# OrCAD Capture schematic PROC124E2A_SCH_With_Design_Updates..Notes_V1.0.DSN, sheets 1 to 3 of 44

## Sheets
1 23. CPSW RGMII_2 ETHERNET PHY: size C; title: CPSW RGMII_1 ETHERNET PHY; rev: E2A
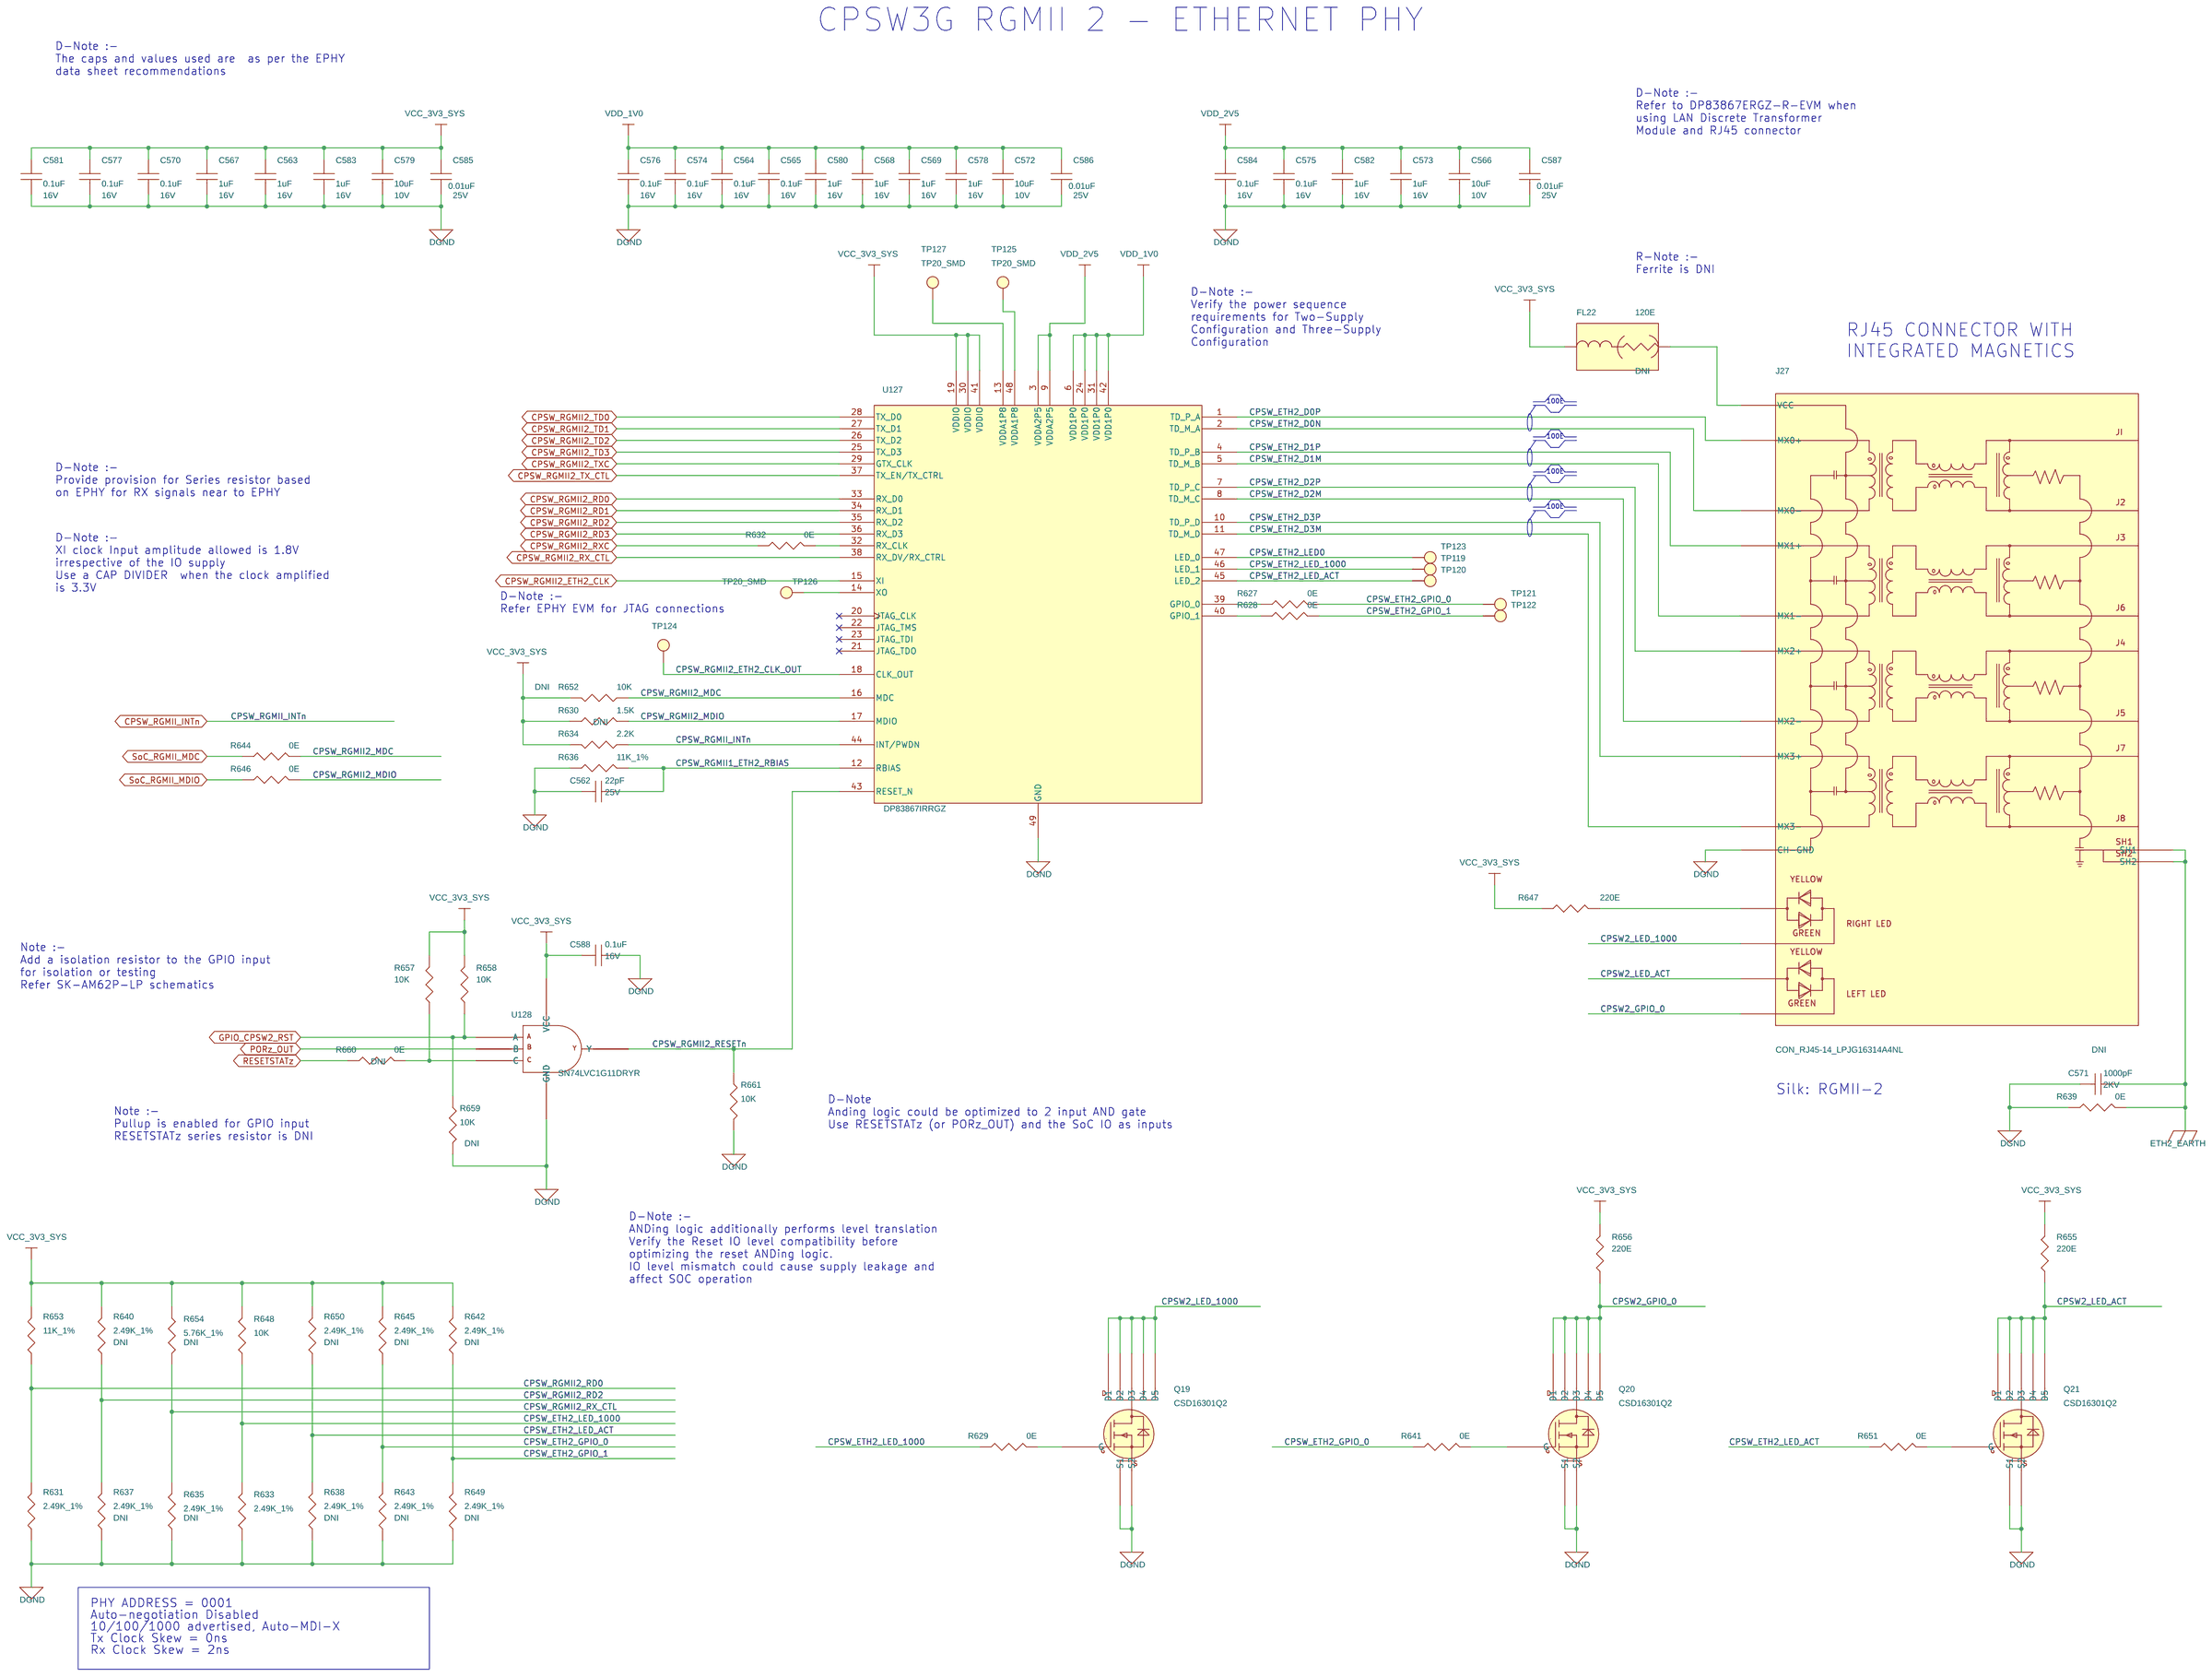
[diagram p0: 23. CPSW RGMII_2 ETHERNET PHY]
2 43. CAN FD WKUP SW: size C; title: CAN FD WKUP SW
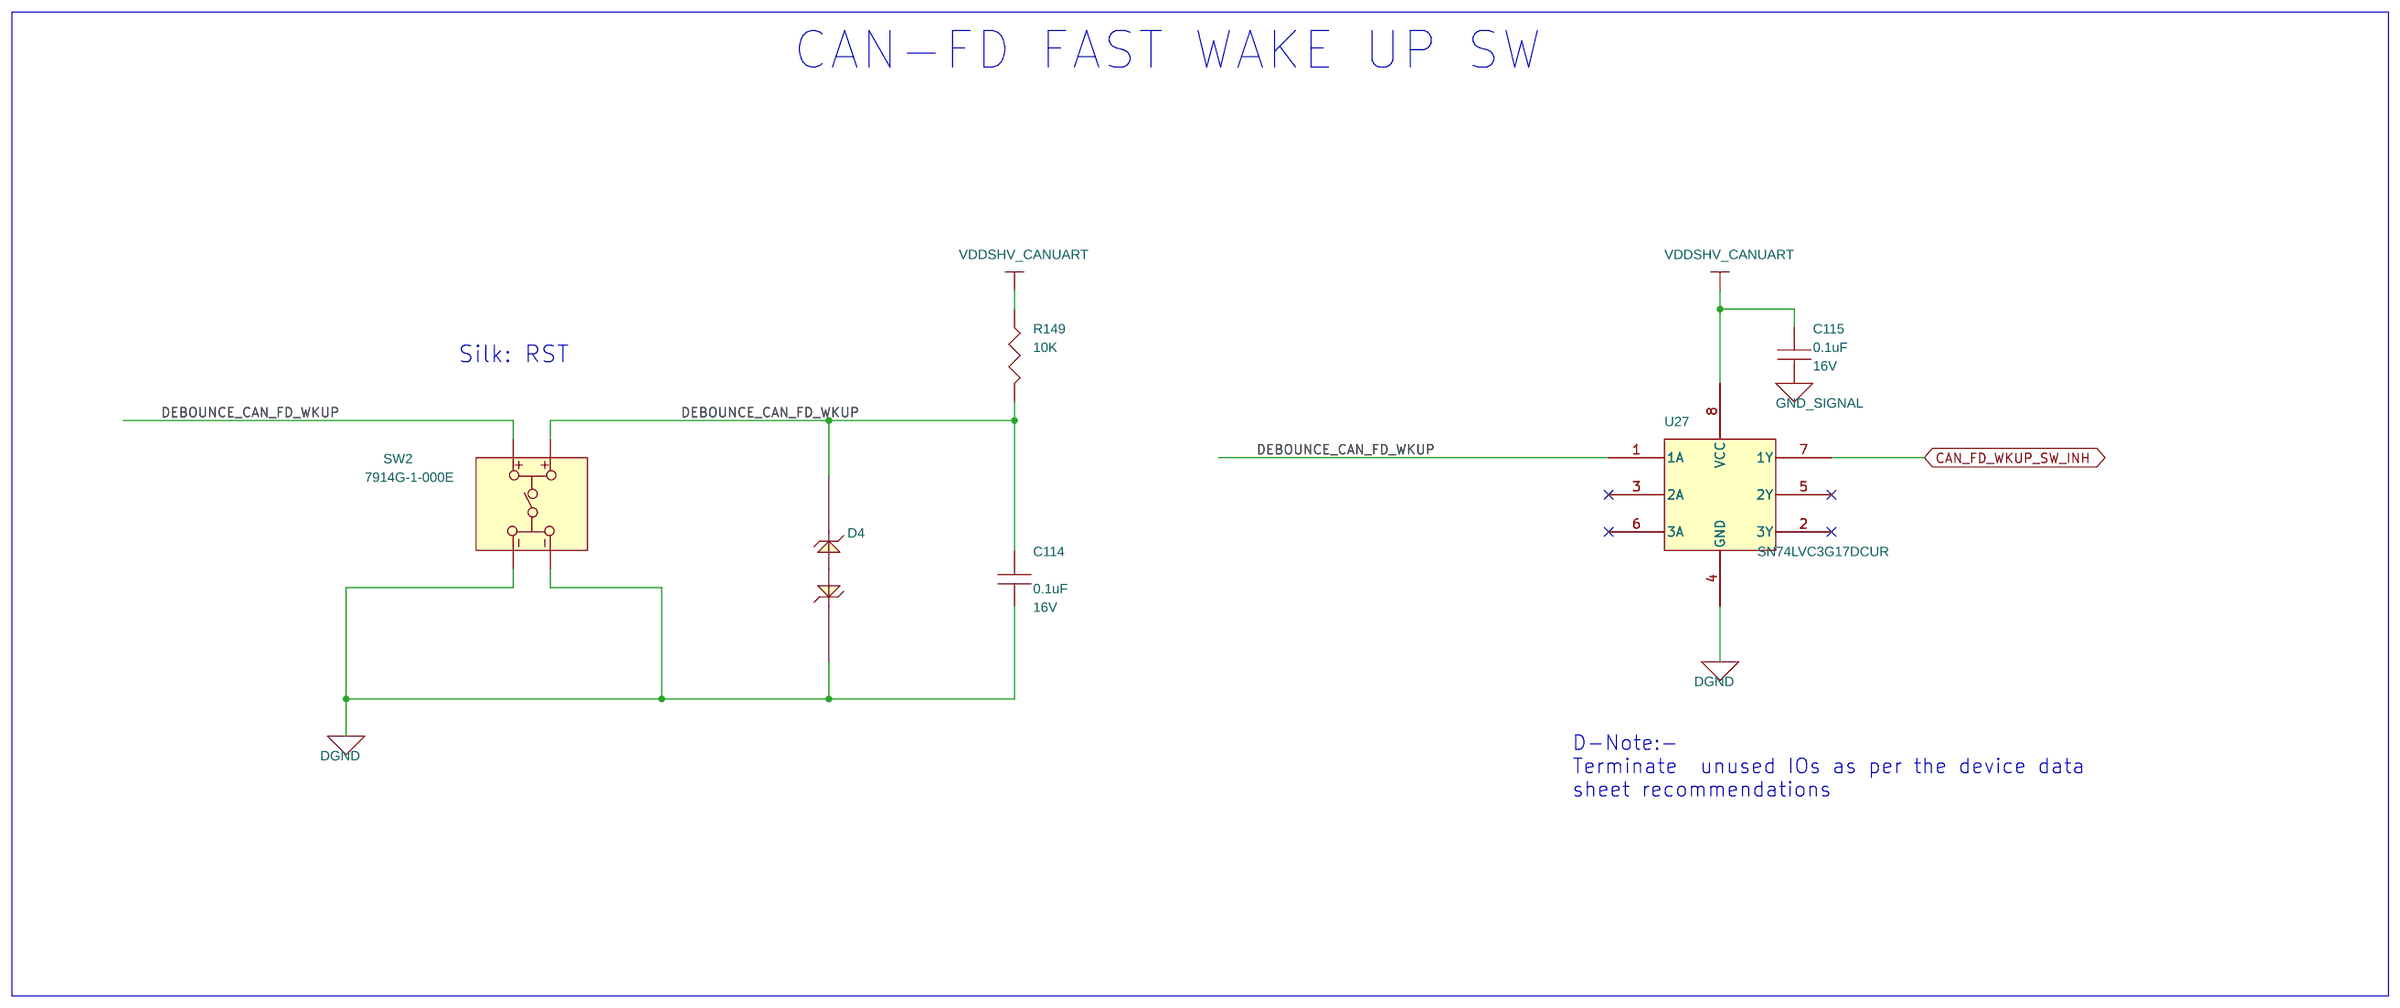
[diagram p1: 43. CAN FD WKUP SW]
3 16. LPDDR4 INTERFACE: size C; title: SOC LPDDR4 INTERFACE
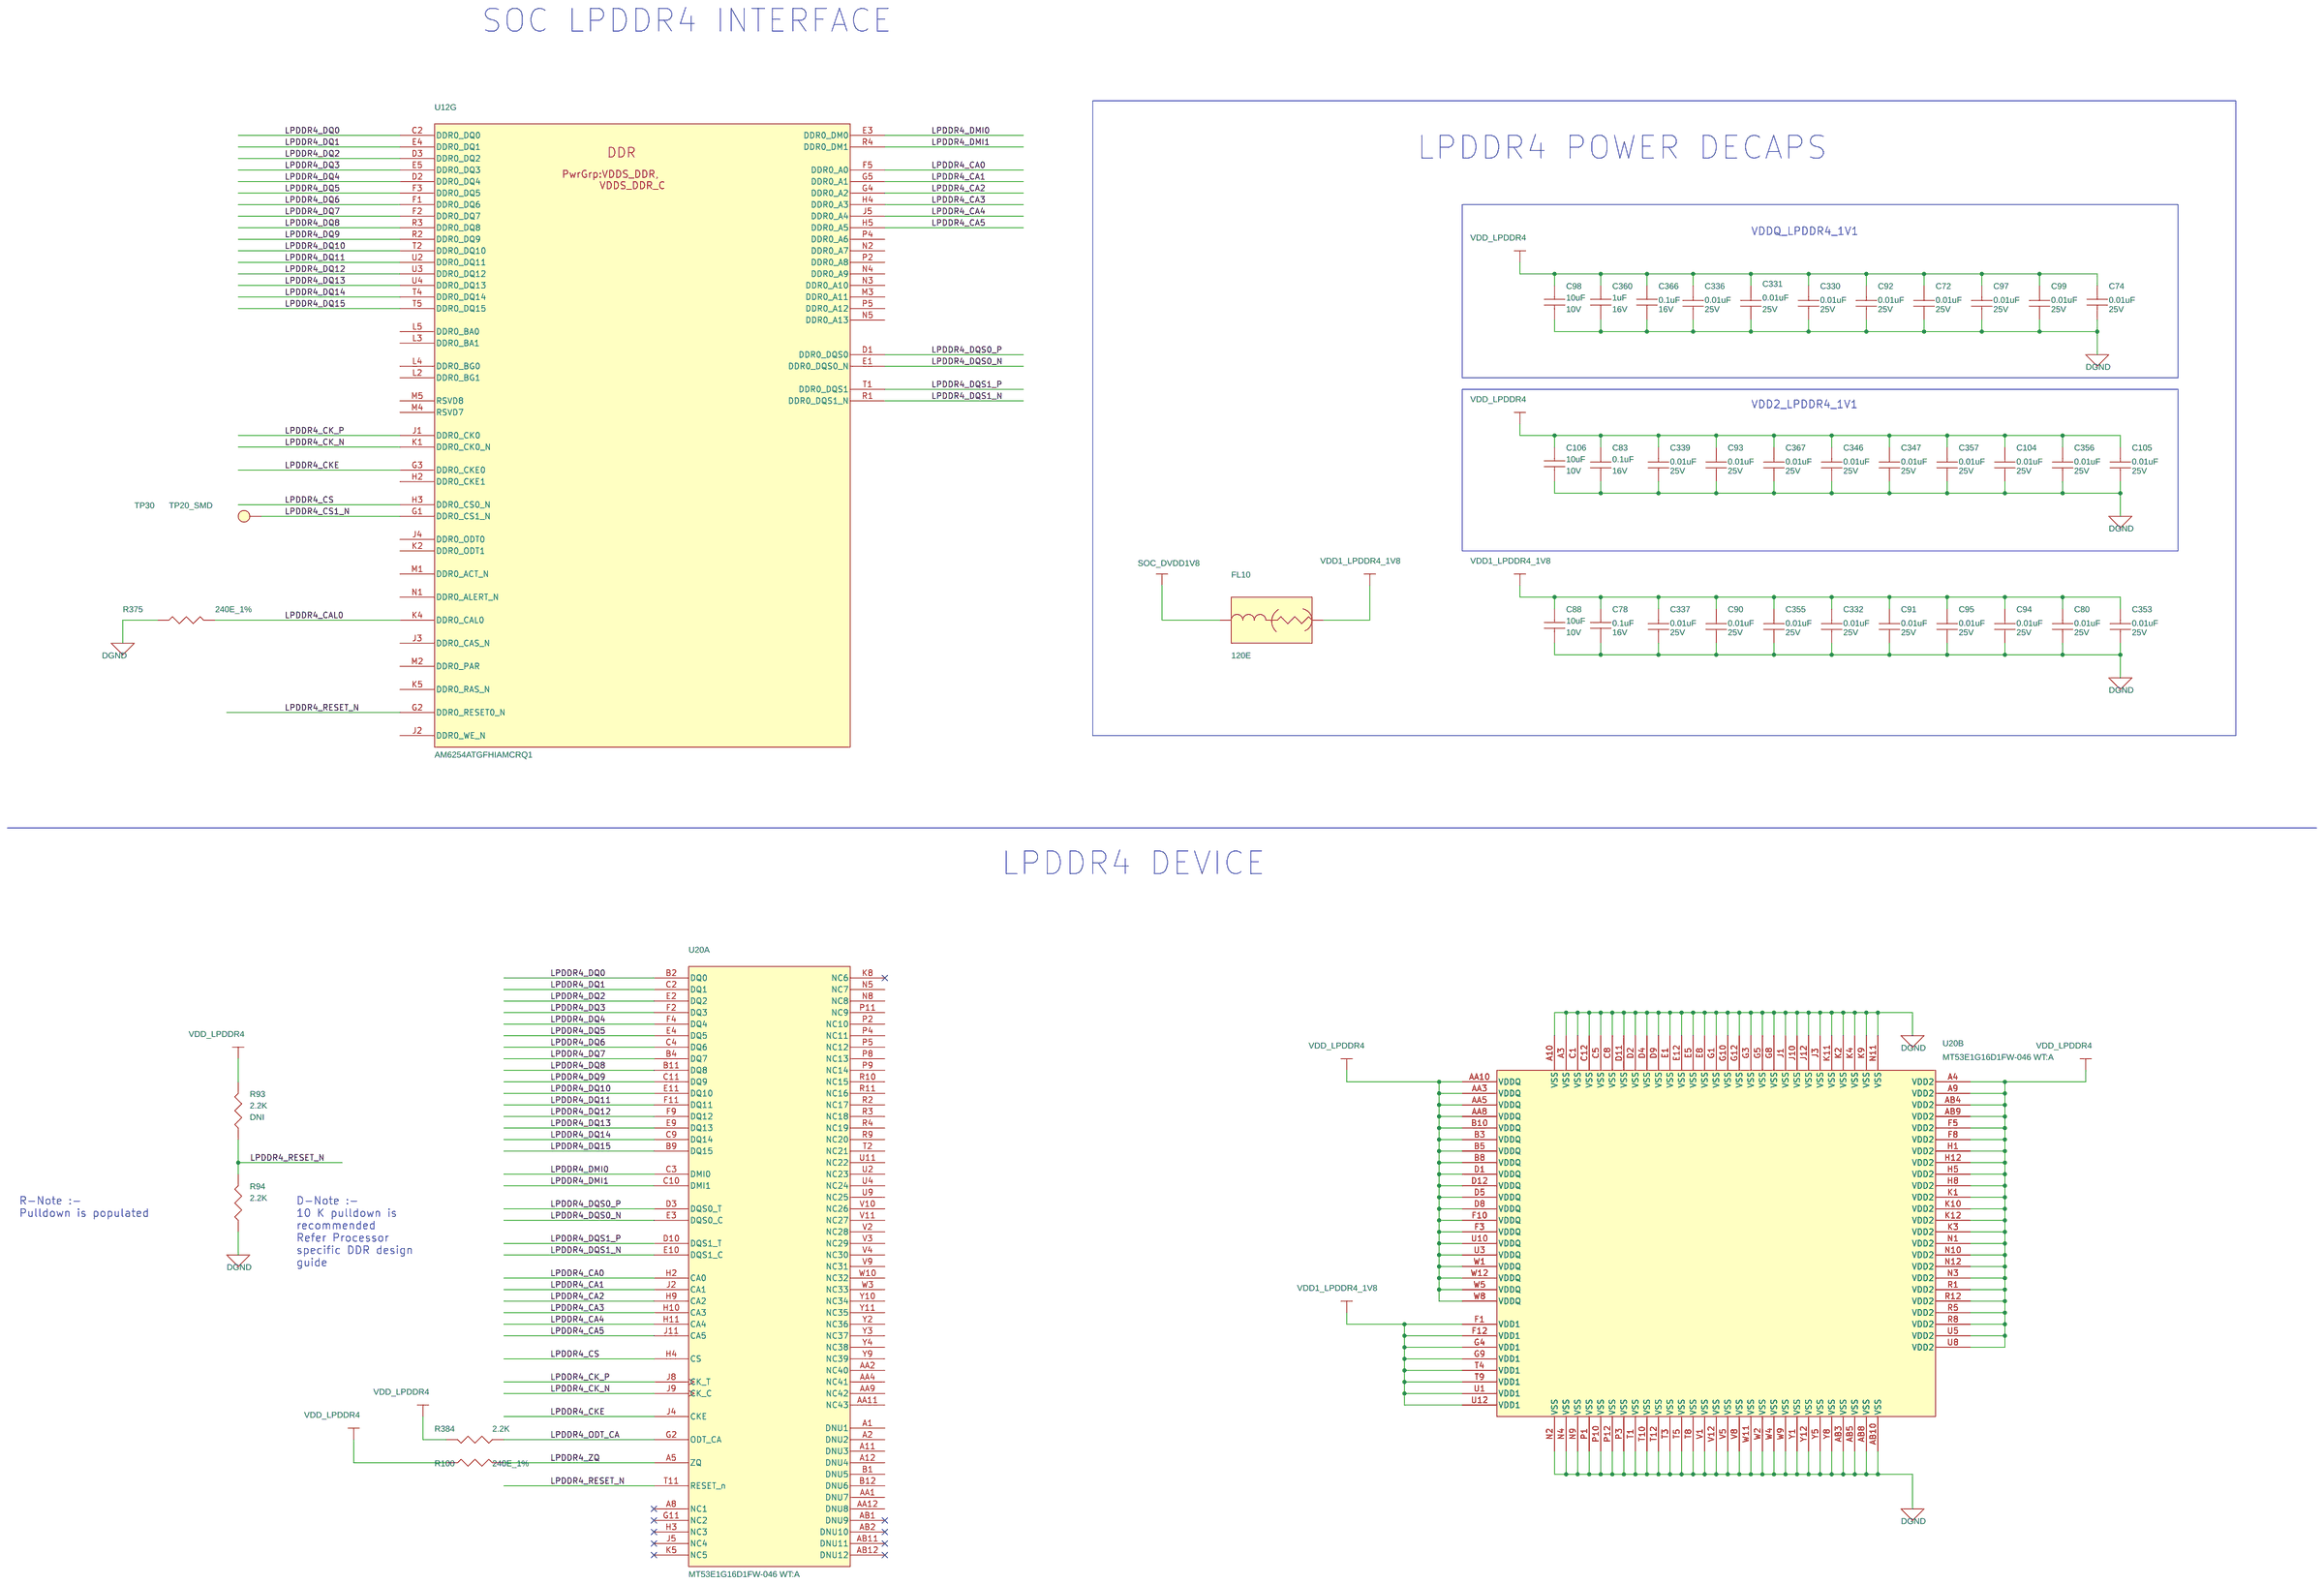
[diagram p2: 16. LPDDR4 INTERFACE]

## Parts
sheet 15. SOC POWER CAPS
U12  AM6254ATGFHIAMCRQ1  [FCBGA441_31-49_680X680_2-6]  (sections A,B,C,D,E,F,G,H,I,J,K,L,M,N,O,P,Q,R)
sheet 16. LPDDR4 INTERFACE
C72  0.01uF  [CAP0201_0-5]
C74  0.01uF  [CAP0201_0-5]
C78  0.1uF  [CAP0201_0-5]
C80  0.01uF  [CAP0201_0-5]
C83  0.1uF  [CAP0201_0-5]
C88  10uF  [CAP0402_0-75]
C90  0.01uF  [CAP0201_0-5]
C91  0.01uF  [CAP0201_0-5]
C92  0.01uF  [CAP0201_0-5]
C93  0.01uF  [CAP0201_0-5]
C94  0.01uF  [CAP0201_0-5]
C95  0.01uF  [CAP0201_0-5]
C97  0.01uF  [CAP0201_0-5]
C98  10uF  [CAP0402_0-75]
C99  0.01uF  [CAP0201_0-5]
C104  0.01uF  [CAP0201_0-5]
C105  0.01uF  [CAP0201_0-5]
C106  10uF  [CAP0402_0-75]
C330  0.01uF  [CAP0201_0-5]
C331  0.01uF  [CAP0201_0-5]
C332  0.01uF  [CAP0201_0-5]
C336  0.01uF  [CAP0201_0-5]
C337  0.01uF  [CAP0201_0-5]
C339  0.01uF  [CAP0201_0-5]
C346  0.01uF  [CAP0201_0-5]
C347  0.01uF  [CAP0201_0-5]
C353  0.01uF  [CAP0201_0-5]
C355  0.01uF  [CAP0201_0-5]
C356  0.01uF  [CAP0201_0-5]
C357  0.01uF  [CAP0201_0-5]
C360  1uF  [CAP0201_0-5]
C366  0.1uF  [CAP0201_0-5]
C367  0.01uF  [CAP0201_0-5]
FL10  120E  [EMIFIL_BLM15A_0402_0-6]
R93  2.2K  [RES0402_0-5]
R94  2.2K  [RES0402_0-5]
R100  240E_1%  [RES0402_0-5]
R375  240E_1%  [RES0402_0-5]
R384  2.2K  [RES0402_0-5]
TP30  TP20_SMD  [TP20_SMD]
U20  MT53E1G16D1FW-046 WT:A  [TFBGA200_MT53E1G16D1FW_400X570_1-1]  (sections A,B)
sheet 23. CPSW RGMII_2 ETHERNET PHY
C562  22pF  [CAP0201_0-5]
C563  1uF  [CAP0201_0-5]
C564  0.1uF  [CAP0201_0-5]
C565  0.1uF  [CAP0201_0-5]
C566  10uF  [CAP0402_0-75]
C567  1uF  [CAP0201_0-5]
C568  1uF  [CAP0201_0-5]
C569  1uF  [CAP0201_0-5]
C570  0.1uF  [CAP0201_0-5]
C571  1000pF  [CAP1206_1-75]
C572  10uF  [CAP0402_0-75]
C573  1uF  [CAP0201_0-5]
C574  0.1uF  [CAP0201_0-5]
C575  0.1uF  [CAP0201_0-5]
C576  0.1uF  [CAP0201_0-5]
C577  0.1uF  [CAP0201_0-5]
C578  1uF  [CAP0201_0-5]
C579  10uF  [CAP0402_0-75]
C580  1uF  [CAP0201_0-5]
C581  0.1uF  [CAP0201_0-5]
C582  1uF  [CAP0201_0-5]
C583  1uF  [CAP0201_0-5]
C584  0.1uF  [CAP0201_0-5]
C585  0.01uF  [CAP0201_0-5]
C586  0.01uF  [CAP0201_0-5]
C587  0.01uF  [CAP0201_0-5]
C588  0.1uF  [CAP0201_0-5]
FL22  120E  [EMIFIL_BLM15A_0402_0-6]
J27  CON_RJ45-14_LPJG16314A4NL  [CON_RJ45-14_LPJG16314A4NL_S_R_T_13-6]
Q19  CSD16301Q2  [WSON6_CSD13202Q2_80X80_0-8]
Q20  CSD16301Q2  [WSON6_CSD13202Q2_80X80_0-8]
Q21  CSD16301Q2  [WSON6_CSD13202Q2_80X80_0-8]
R627  0E  [RES0201_0-5]
R628  0E  [RES0201_0-5]
R629  0E  [RES0201_0-5]
R630  1.5K  [RES0201_0-5]
R631  2.49K_1%  [RES0402_0-5]
R632  0E  [RES0402_0-5]
R633  2.49K_1%  [RES0402_0-5]
R634  2.2K  [RES0201_0-5]
R635  2.49K_1%  [RES0402_0-5]
R636  11K_1%  [RES0402_0-5]
R637  2.49K_1%  [RES0402_0-5]
R638  2.49K_1%  [RES0402_0-5]
R639  0E  [RES0603_0-75]
R640  2.49K_1%  [RES0402_0-5]
R641  0E  [RES0201_0-5]
R642  2.49K_1%  [RES0402_0-5]
R643  2.49K_1%  [RES0402_0-5]
R644  0E  [RES0402_0-5]
R645  2.49K_1%  [RES0402_0-5]
R646  0E  [RES0402_0-5]
R647  220E  [RES0402_0-5]
R648  10K  [RES0201_0-5]
R649  2.49K_1%  [RES0402_0-5]
R650  2.49K_1%  [RES0402_0-5]
R651  0E  [RES0201_0-5]
R652  10K  [RES0201_0-5]
R653  11K_1%  [RES0402_0-5]
R654  5.76K_1%  [RES0402_0-5]
R655  220E  [RES0402_0-5]
R656  220E  [RES0402_0-5]
R657  10K  [RES0201_0-5]
R658  10K  [RES0201_0-5]
R659  10K  [RES0201_0-5]
R660  0E  [RES0201_0-5]
R661  10K  [RES0201_0-5]
TP119  TP20_SMD  [TP20_SMD]
TP120  TP20_SMD  [TP20_SMD]
TP121  TP20_SMD  [TP20_SMD]
TP122  TP20_SMD  [TP20_SMD]
TP123  TP20_SMD  [TP20_SMD]
TP124  TP20_SMD  [TP20_SMD]
TP125  TP20_SMD  [TP20_SMD]
TP126  TP20_SMD  [TP20_SMD]
TP127  TP20_SMD  [TP20_SMD]
U127  DP83867IRRGZ  [QFN48_19-68_280X280_1]
U128  SN74LVC1G11DRYR  [SON6_SN74LVC2G17_40X60_0-6]
sheet 43. CAN FD WKUP SW
C114  0.1uF  [CAP0201_0-5]
C115  0.1uF  [CAP0201_0-5]
D4  TPD1E10B06DPYR  [DIO_DFN0402_0-5]
R149  10K  [RES0201_0-5]
SW2  7914G-1-000E  [SW4_100X216_200X200_SMD_4-2]
U27  SN74LVC3G17DCUR  [VSSOP8_19-68_85X95_0-9]

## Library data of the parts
U12 = AM6254ATGFHIAMCRQ1_FCBGA441: IC AM62Q SoC MICROPROCESSOR FCBGA441; Chkd/date: PRADEEP/180324; Crtd /date: TAMILARASU/180324; Custom_Duty: 15%; Customs_HS_Code: 85423100; Distributor_name: NA; Distributor_part_number: NA; Footprint Path: Y:\MIS_DATABASE\Library\ALTIUM_TOOL\PCB_FOOTPRINTS\Altium_Footprint_Lib.PcbLib; Height: 2.57MM; Library Path: Y:\MIS_DATABASE\Library\ALTIUM_TOOL\SCHEMATICS_PARTS\MS_MICROPROCESSOR_Library.schlib; Mfr_name: TEXAS INSTRUMENTS; Mistral Part No: 141224030001-R; Package: FCBGA441; Part_type: ICS\DIGITAL\MICROPROCESSOR; Project: TI_AM62Q_BRD; RoHS: NA; Temperature: NA; Tolerance: NA; Voltage: NA; Wattage: NA; Weight: NA; Datasheet: Y:\MIS_DATABASE\DATASHEETS\ICS\DIGITAL\MICROCONTROLLER\AM62Q-SoC.PDF
C72 C74 C80 C90-C95 C97 C99 C104 C105 C330-C332 C336 C337 C339 C346 C347 C353 C355-C357 C367 = CAP: CAP CERAMIC 0.01uF 25V 10% X7R 0201; Chkd/date: MANIRAJA/080519; Crtd /date: ALVY/080519; Custom_Duty: 15%; Customs_HS_Code: 85322990; Distributor_name: DIGIKEY; Distributor_part_number: 490-14454-1-ND; Footprint Path: Y:\MIS_DATABASE\Library\ALTIUM_TOOL\PCB_FOOTPRINTS\Altium_Footprint_Lib.PcbLib; Height: 0.33MM; Library Path: Y:\MIS_DATABASE\Library\ALTIUM_TOOL\SCHEMATICS_PARTS\MS_DISCRETE_Library.schlib; Mfr_name: MURATA; Mfr_part_number: GRM033R71E103KE14D; Mistral Part No: 120019050002-R; Package: 0201; Part_type: CAPACITORS\CERAMIC; Project: BRUKER_SD820_COMMONDO; RoHS: RoHS; Temperature: -55°C+125°C; Tolerance: 10%; Voltage: 25V; Wattage: NA; Weight: 0.33mg; Datasheet: Y:\MIS_DATABASE\DATASHEETS\CAPACITORS\GRM033R71E103KE14.PDF
C78 C83 C366 = CAP: CAP CERAMIC 0.1uF 16V 10% X5R 0201; Chkd/date: MANIRAJA/230118; Crtd /date: MANIRAJA/230118; Custom_Duty: 15%; Customs_HS_Code: 85322990; Distributor_name: DIGIKEY; Distributor_part_number: 490-14305-1-ND; Footprint Path: Y:\MIS_DATABASE\Library\ALTIUM_TOOL\PCB_FOOTPRINTS\Altium_Footprint_Lib.PcbLib; Height: 0.33MM; Library Path: Y:\MIS_DATABASE\Library\ALTIUM_TOOL\SCHEMATICS_PARTS\MS_DISCRETE_Library.schlib; Mfr_name: MURATA; Mfr_part_number: GRM033R61C104KE14D; Mistral Part No: 120009030072-R; Package: 0201; Part_type: CAPACITORS\CERAMIC; Project: TI_MAXIE_CPB; RoHS: RoHS; Temperature: -55°C+85°C; Tolerance: 10%; Voltage: 16V; Wattage: NA; Weight: 0.33mg; Datasheet: Y:\MIS_DATABASE\DATASHEETS\CAPACITORS\GRM033R61C104KE14.PDF
C88 C98 C106 C566 C572 C579 = CAP: CAP CERAMIC 10uF 10V 20% X5R 0402; Chkd/date: MANIRAJA/300520; Crtd /date: ALVY/260520; Custom_Duty: 15%; Customs_HS_Code: 85322990; Distributor_name: DIGIKEY; Distributor_part_number: 490-GRM155R61A106ME11DTR-ND; Footprint Path: Y:\MIS_DATABASE\Library\ALTIUM_TOOL\PCB_FOOTPRINTS\Altium_Footprint_Lib.PcbLib; Height: 0.55MM; Library Path: Y:\MIS_DATABASE\Library\ALTIUM_TOOL\SCHEMATICS_PARTS\MS_DISCRETE_Library.schlib; Mfr_name: MURATA; Mfr_part_number: GRM155R61A106ME11D; Mistral Part No: 120013110019-R; Package: 0402; Part_type: CAPACITORS\CERAMIC; Project: QCS610_NANOSOM; RoHS: RoHS; Temperature: -55°C+85°C; Tolerance: 20%; Voltage: 10V; Wattage: NA; Weight: 3.1mg; Datasheet: Y:\MIS_DATABASE\DATASHEETS\CAPACITORS\MURATA-GXX-SER_NOV17.PDF
C360 C563 C567-C569 C573 C578 C580 C582 C583 = CAP: CAP CERAMIC 1uF 16V 20% X5R 0201; Chkd/date: MANIRAJA/300520; Crtd /date: ALVY/260520; Custom_Duty: 15%; Customs_HS_Code: 85322990; Distributor_name: DIGIKEY; Distributor_part_number: 490-18654-1-ND; Footprint Path: Y:\MIS_DATABASE\Library\ALTIUM_TOOL\PCB_FOOTPRINTS\Altium_Footprint_Lib.PcbLib; Height: 0.39MM; Library Path: Y:\MIS_DATABASE\Library\ALTIUM_TOOL\SCHEMATICS_PARTS\MS_DISCRETE_Library.schlib; Mfr_name: MURATA; Mfr_part_number: GRM033R61C105ME15D; Mistral Part No: 120018090038-R; Package: 0201; Part_type: CAPACITORS\CERAMIC; Project: QCS610_NANOSOM; RoHS: RoHS; Temperature: -55°C+85°C; Tolerance: 20%; Voltage: 16V; Wattage: NA; Weight: 0.33mg; Datasheet: Y:\MIS_DATABASE\DATASHEETS\CAPACITORS\GRM033R61C105ME15.PDF
FL10 = EMIFILTER_IND: IND FERRITE BEAD CHIP 120E 2A 0402; Chkd/date: NAVEED/241114; Crtd /date: USMAN/170613; Custom_Duty: 24%; Customs_HS_Code: 85369090; Distributor_name: DIGIKEY; Distributor_part_number: 490-9656-1-ND; Footprint Path: Y:\MIS_DATABASE\Library\ALTIUM_TOOL\PCB_FOOTPRINTS\Altium_Footprint_Lib.PcbLib; Height: 0.55MM; Library Path: Y:\MIS_DATABASE\Library\ALTIUM_TOOL\SCHEMATICS_PARTS\MS_FILTER_Library.schlib; Mfr_name: MURATA; Mfr_part_number: BLM15PX121SN1D; Mistral Part No: 130013060022-R; Package: 0402; Part_type: INDUCTOR; Project: GEN_3-8; RoHS: RoHS; Temperature: -55°C+125°C; Tolerance: 25%; Voltage: NA; Wattage: NA; Weight: 1mg; Datasheet: Y:\MIS_DATABASE\DATASHEETS\DISCRETES\INDUCTORS\BLM15-SN1-SER.PDF
R93 = RESISTOR: RES 2.2K 1/16W 5% 0402; Assembly_Instruction: DNI; Chkd/date: VASANTHA/061216; Crtd /date: BAVISH/021210; Custom_Duty: 15%; Customs_HS_Code: 85332119; Distributor_name: DIGIKEY; Distributor_part_number: 311-2.2KJRCT-ND; Footprint Path: Y:\MIS_DATABASE\Library\ALTIUM_TOOL\PCB_FOOTPRINTS\Altium_Footprint_Lib.PcbLib; Height: 0.40MM; Library Path: Y:\MIS_DATABASE\Library\ALTIUM_TOOL\SCHEMATICS_PARTS\MS_DISCRETE_Library.schlib; Mfr_name: YAGEO AMERICA; Mfr_part_number: RC0402JR-072K2L; Mistral Part No: 110010120018-R; Package: 0402; Part_type: RESISTORS\FIXED; Project: TE4; RoHS: RoHS; Temperature: -55°C+155°C; Tolerance: 5%; Voltage: NA; Wattage: 1/16W; Weight: 0.65mg; Datasheet: Y:\MIS_DATABASE\DATASHEETS\RESISTORS\RCXXXXL-SER_MAR18.PDF
R94 R384 = RESISTOR: RES 2.2K 1/16W 5% 0402; Chkd/date: VASANTHA/061216; Crtd /date: BAVISH/021210; Custom_Duty: 15%; Customs_HS_Code: 85332119; Distributor_name: DIGIKEY; Distributor_part_number: 311-2.2KJRCT-ND; Footprint Path: Y:\MIS_DATABASE\Library\ALTIUM_TOOL\PCB_FOOTPRINTS\Altium_Footprint_Lib.PcbLib; Height: 0.40MM; Library Path: Y:\MIS_DATABASE\Library\ALTIUM_TOOL\SCHEMATICS_PARTS\MS_DISCRETE_Library.schlib; Mfr_name: YAGEO AMERICA; Mfr_part_number: RC0402JR-072K2L; Mistral Part No: 110010120018-R; Package: 0402; Part_type: RESISTORS\FIXED; Project: TE4; RoHS: RoHS; Temperature: -55°C+155°C; Tolerance: 5%; Voltage: NA; Wattage: 1/16W; Weight: 0.65mg; Datasheet: Y:\MIS_DATABASE\DATASHEETS\RESISTORS\RCXXXXL-SER_MAR18.PDF
R100 R375 = RESISTOR: RES 240E 1/10W 1% 0402; Chkd/date: MAZHAR/150611; Crtd /date: BAVISH/020611; Custom_Duty: 15%; Customs_HS_Code: 85332119; Distributor_name: DIGIKEY; Distributor_part_number: P240LCT-ND; Footprint Path: Y:\MIS_DATABASE\Library\ALTIUM_TOOL\PCB_FOOTPRINTS\Altium_Footprint_Lib.PcbLib; Height: 0.40MM; Library Path: Y:\MIS_DATABASE\Library\ALTIUM_TOOL\SCHEMATICS_PARTS\MS_DISCRETE_Library.schlib; Mfr_name: PANASONIC-ECG; Mfr_part_number: ERJ-2RKF2400X; Mistral Part No: 110011060017-R; Package: 0402; Part_type: RESISTORS\FIXED; Project: AM4515_EVM_LCD; RoHS: RoHS; Temperature: -55°C+155°C; Tolerance: 1%; Voltage: NA; Wattage: 1/10W; Weight: 0.8mg; Datasheet: Y:\MIS_DATABASE\DATASHEETS\RESISTORS\PAN-ERJSER_NOV17.PDF
TP30 TP119-TP124 = TESTPOINT: TESTPOINT CIR 20 SMD; Chkd/date: SHREESHAIL/171006; Crtd /date: MAZHAR/171006; Custom_Duty: NA; Customs_HS_Code: NA; Distributor_name: NA; Distributor_part_number: NA; Footprint Path: Y:\MIS_DATABASE\Library\ALTIUM_TOOL\PCB_FOOTPRINTS\Altium_Footprint_Lib.PcbLib; Height: NA; Library Path: Y:\MIS_DATABASE\Library\ALTIUM_TOOL\SCHEMATICS_PARTS\MS_DISCRETE_Library.schlib; MECHANICAL 3D STEP FILE: NA; Mfr_name: LOCAL; Mistral Part No: NA; Package: SMD; Project: BT MODULE_CSRBC04; RoHS: NA; Temperature: NA; Tolerance: NA; Voltage: NA; Wattage: NA; Weight: NA; Datasheet: NA
U20 = MT53E1G16D1FW_TFBGA200: IC 16Gb AUTOMOTIVE LPDDR4 SDRAM TFBGA200; Chkd/date: MANIRAJA/140920; Crtd /date: ALVY/140920; Custom_Duty: 15%; Customs_HS_Code: 85423100; Distributor_name: MOUSER; Distributor_part_number: 340-440766-TRAY; Footprint Path: Y:\MIS_DATABASE\Library\ALTIUM_TOOL\PCB_FOOTPRINTS\Altium_Footprint_Lib.PcbLib; Height: 1.10MM; Library Path: Y:\MIS_DATABASE\Library\ALTIUM_TOOL\SCHEMATICS_PARTS\MS_MISCMEMORY_Library.schlib; Mfr_name: MICRON; Mistral Part No: 141120090005-R; Package: TFBGA200; Part_type: ICS\DIGITAL\MEMORY; Project: AM64X_SKEVM; Remarks: PAD CHANGED AS PER TI RECOMMENDATION; RoHS: RoHS; Temperature: -25°C+85°C; Tolerance: NA; Voltage: NA; Wattage: NA; Weight: NA; Datasheet: Y:\MIS_DATABASE\DATASHEETS\ICS\MEMORY\MT53E1GXXDXX-SER.PDF
C562 = CAP: CAP CERAMIC 22pF 25V 1% C0G(NP0) 0201; Chkd/date: MANIRAJA/270721; Crtd /date: ALVY/260721; Custom_Duty: 15%; Customs_HS_Code: 85322990; Distributor_name: DIGIKEY; Distributor_part_number: 490-14545-1-ND; Footprint Path: Y:\MIS_DATABASE\Library\ALTIUM_TOOL\PCB_FOOTPRINTS\Altium_Footprint_Lib.PcbLib; Height: 0.33MM; Library Path: Y:\MIS_DATABASE\Library\ALTIUM_TOOL\SCHEMATICS_PARTS\MS_DISCRETE_Library.schlib; Mfr_name: MURATA; Mfr_part_number: GRM0335C1E220FA01D; Mistral Part No: 120021070019-R; Package: 0201; Part_type: CAPACITORS\CERAMIC; Project: TI_AM335x SK_BRD; RoHS: RoHS; Temperature: -55°C+125°C; Tolerance: 1%; Voltage: 25V; Wattage: NA; Weight: 0.33mg; Datasheet: Y:\MIS_DATABASE\DATASHEETS\CAPACITORS\GRM0335C1E220FA01.PDF
C114 C115 C564 C565 C570 C574-C577 C581 C584 C588 = CAP: CAP CERAMIC 0.1uF 16V 10% X5R 0201; Alt_Mfr_name: YAGEO AMERICA; Alt_Mfr_part_number: CC0402KRX5R8BB104; Chkd/date: MANIRAJA/230118; Crtd /date: MANIRAJA/230118; Custom_Duty: 15%; Customs_HS_Code: 85322990; Distributor_name: DIGIKEY; Distributor_part_number: 490-14305-1-ND; Footprint Path: Y:\MIS_DATABASE\Library\ALTIUM_TOOL\PCB_FOOTPRINTS\Altium_Footprint_Lib.PcbLib; Height: 0.33MM; Library Path: Y:\MIS_DATABASE\Library\ALTIUM_TOOL\SCHEMATICS_PARTS\MS_DISCRETE_Library.schlib; Mfr_name: MURATA; Mfr_part_number: GRM033R61C104KE14D; Mistral Part No: 120009030072-R; Package: 0201; Part_type: CAPACITORS\CERAMIC; Project: TI_MAXIE_CPB; RoHS: RoHS; Temperature: -55°C+85°C; Tolerance: 10%; Voltage: 16V; Wattage: NA; Weight: 0.33mg; Datasheet: Y:\MIS_DATABASE\DATASHEETS\CAPACITORS\GRM033R61C104KE14.PDF
C571 = CAP: CAP CERAMIC 1000pF 2KV 10% X7R 1206; Assembly_Instruction: DNI; Chkd/date: SHREESHAIL/291106; Crtd /date: MAZHAR/281106; Custom_Duty: 15%; Customs_HS_Code: 85322990; Distributor_name: DIGIKEY; Distributor_part_number: 478-2956-1-ND; Footprint Path: Y:\MIS_DATABASE\Library\ALTIUM_TOOL\PCB_FOOTPRINTS\Altium_Footprint_Lib.PcbLib; Height: 1.52MM; Library Path: Y:\MIS_DATABASE\Library\ALTIUM_TOOL\SCHEMATICS_PARTS\MS_DISCRETE_Library.schlib; Mfr_name: AVX CORPORATION; Mfr_part_number: 1206GC102KAT1A; Mistral Part No: 120015080006-R; Package: 1206; Part_type: CAPACITORS\CERAMIC; Project: ADR1B; RoHS: RoHS; Temperature: -55°C+125°C; Tolerance: 10%; Voltage: 2KV; Wattage: NA; Weight: 16.2mg; Datasheet: Y:\MIS_DATABASE\DATASHEETS\CAPACITORS\AVX_HV-MLC.PDF
C585-C587 = CAP: CAP CERAMIC 0.01uF 25V 10% X5R 0201; Chkd/date: MANIRAJA/230118; Crtd /date: MANIRAJA/230118; Custom_Duty: 15%; Customs_HS_Code: 85322990; Distributor_name: DIGIKEY; Distributor_part_number: GRM033R61E103KA12J-ND; Footprint Path: Y:\MIS_DATABASE\Library\ALTIUM_TOOL\PCB_FOOTPRINTS\Altium_Footprint_Lib.PcbLib; Height: 0.33MM; Library Path: Y:\MIS_DATABASE\Library\ALTIUM_TOOL\SCHEMATICS_PARTS\MS_DISCRETE_Library.schlib; Mfr_name: MURATA; Mfr_part_number: GRM033R61E103KA12J; Mistral Part No: 120018010007-R; Package: 0201; Part_type: CAPACITORS\CERAMIC; Project: TI_MAXIE_CPB; RoHS: RoHS; Temperature: -55°C+85°C; Tolerance: 10%; Voltage: 25V; Wattage: NA; Weight: 0.33mg; Datasheet: Y:\MIS_DATABASE\DATASHEETS\CAPACITORS\GRM033R61E103KA12.PDF
FL22 = EMIFILTER_IND: IND FERRITE BEAD CHIP 120E 2A 0402; Assembly_Instruction: DNI; Chkd/date: NAVEED/241114; Crtd /date: USMAN/170613; Custom_Duty: 24%; Customs_HS_Code: 85369090; Distributor_name: DIGIKEY; Distributor_part_number: 490-9656-1-ND; Footprint Path: Y:\MIS_DATABASE\Library\ALTIUM_TOOL\PCB_FOOTPRINTS\Altium_Footprint_Lib.PcbLib; Height: 0.55MM; Library Path: Y:\MIS_DATABASE\Library\ALTIUM_TOOL\SCHEMATICS_PARTS\MS_FILTER_Library.schlib; Mfr_name: MURATA; Mfr_part_number: BLM15PX121SN1D; Mistral Part No: 130013060022-R; Package: 0402; Part_type: INDUCTOR; Project: GEN_3-8; RoHS: RoHS; Temperature: -55°C+125°C; Tolerance: 25%; Voltage: NA; Wattage: NA; Weight: 1mg; Datasheet: Y:\MIS_DATABASE\DATASHEETS\DISCRETES\INDUCTORS\BLM15-SN1-SER.PDF
J27 = CON_RJ45-14_LPJG16314A4NL: CON RJ-45 FEMALE 14POS RT TH; Chkd/date: VASANTHA/150714; Crtd /date: BALACHANDAR/120614; Custom_Duty: 24%; Customs_HS_Code: 85369090; Distributor_name: NA; Distributor_part_number: NA; Footprint Path: Y:\MIS_DATABASE\Library\ALTIUM_TOOL\PCB_FOOTPRINTS\Altium_Footprint_Lib.PcbLib; Height: 13.60MM; Library Path: Y:\MIS_DATABASE\Library\ALTIUM_TOOL\SCHEMATICS_PARTS\MS_CONNECTOR_Library.schlib; Mfr_name: LINK-PP; Mfr_part_number: LPJG16314A4NL; Mistral Part No: 150014060029-R; Package: THRU-HOLE; Part_type: CONNECTOR\JACK; Project: AEGIS; RoHS: RoHS; Temperature: -0°C+70°C; Tolerance: NA; Voltage: NA; Wattage: NA; Weight: NA; Datasheet: Y:\MIS_DATABASE\DATASHEETS\CONNECTORS\LPJG16314A4NL.PDF
Q19-Q21 = MOSFET_CSD17313Q2: IC MOSFET N-CHANNEL NEXFET 25V WSON6; Chkd/date: ALVY/071220; Crtd /date: MANIRAJA/071220; Custom_Duty: 15%; Customs_HS_Code: 85423100; Distributor_name: DIGIKEY; Distributor_part_number: 296-25260-1-ND; Footprint Path: Y:\MIS_DATABASE\Library\ALTIUM_TOOL\PCB_FOOTPRINTS\Altium_Footprint_Lib.PcbLib; Height: 0.80MM; Library Path: Y:\MIS_DATABASE\Library\ALTIUM_TOOL\SCHEMATICS_PARTS\MS_MOSFET_Library.schlib; Manufacturer: TEXAS INSTRUMENTS; Mfr_name: TEXAS INSTRUMENTS; Mistral Part No: 142020120008-R; Package: WSON6; Part_type: ICS\POWER\MOSFET; Project: TI_AM243x LP EVM; RoHS: RoHS; Temperature: -55°C+150°C; Tolerance: NA; Voltage: NA; Wattage: NA; Weight: 8.7mg; Datasheet: Y:\MIS_DATABASE\DATASHEETS\ICS\POWER\CSD16301Q2.PDF
R627-R629 R641 R651 = RESISTOR: RES 0E 1/20W 5% 0201; Chkd/date: NAVEED/301214; Crtd /date: MUDDU/120710; Custom_Duty: 15%; Customs_HS_Code: 85332119; Distributor_name: DIGIKEY; Distributor_part_number: 311-0.0NCT-ND; Footprint Path: Y:\MIS_DATABASE\Library\ALTIUM_TOOL\PCB_FOOTPRINTS\Altium_Footprint_Lib.PcbLib; Height: 0.26MM; Library Path: Y:\MIS_DATABASE\Library\ALTIUM_TOOL\SCHEMATICS_PARTS\MS_DISCRETE_Library.schlib; Mfr_name: YAGEO AMERICA; Mfr_part_number: RC0201JR-070RL; Mistral Part No: 110010070067-R; Package: 0201; Part_type: RESISTORS\FIXED; Project: PB_BUGBASE; RoHS: RoHS; Temperature: -55°C+125°C; Tolerance: 5%; Voltage: NA; Wattage: 1/20W; Weight: 0.17mg; Datasheet: Y:\MIS_DATABASE\DATASHEETS\RESISTORS\RCXXXXL-SER_MAR18.PDF
R630 = RESISTOR: RES 1.5K 1/20W 5% 0201; Assembly_Instruction: DNI; Chkd/date: MAZHAR/130208; Crtd /date: USMAN/130208; Custom_Duty: 15%; Customs_HS_Code: 85332119; Distributor_name: DIGIKEY; Distributor_part_number: P1.5KAGCT-ND; Footprint Path: Y:\MIS_DATABASE\Library\ALTIUM_TOOL\PCB_FOOTPRINTS\Altium_Footprint_Lib.PcbLib; Height: 0.26MM; Library Path: Y:\MIS_DATABASE\Library\ALTIUM_TOOL\SCHEMATICS_PARTS\MS_DISCRETE_Library.schlib; Mfr_name: PANASONIC-ECG; Mfr_part_number: ERJ-1GEJ152C; Mistral Part No: 110010070057-R; Package: 0201; Part_type: RESISTORS\FIXED; Project: SMART VIEW_IP CAMERA; RoHS: RoHS; Temperature: -55°C+125°C; Tolerance: 5%; Voltage: NA; Wattage: 1/20W; Weight: 0.15mg; Datasheet: Y:\MIS_DATABASE\DATASHEETS\RESISTORS\PAN-ERJXGE-FEB06.PDF
R631 R633 = RESISTOR: RES 2.49K 1/16W 1% 0402; Chkd/date: VASANTHA/270516; Crtd /date: VASANTHA/270516; Custom_Duty: 15%; Customs_HS_Code: 85332119; Distributor_name: DIGIKEY; Distributor_part_number: 311-2.49KLRCT-ND; Footprint Path: Y:\MIS_DATABASE\Library\ALTIUM_TOOL\PCB_FOOTPRINTS\Altium_Footprint_Lib.PcbLib; Height: 0.40MM; Library Path: Y:\MIS_DATABASE\Library\ALTIUM_TOOL\SCHEMATICS_PARTS\MS_DISCRETE_Library.schlib; Mfr_name: YAGEO AMERICA; Mfr_part_number: RC0402FR-072K49L; Mistral Part No: 110016050020-R; Package: 0402; Part_type: RESISTORS\FIXED; Project: TMDXCSKCC; RoHS: RoHS; Temperature: -55°C+155°C; Tolerance: 1%; Voltage: NA; Wattage: 1/16W; Weight: 0.65mg; Datasheet: Y:\MIS_DATABASE\DATASHEETS\RESISTORS\RCXXXXL-SER_MAR18.PDF
R632 = RESISTOR: RES 0E 1/16W JUMPER 0402; Chkd/date: VASANTHA/201216; Crtd /date: MUDDU/190810; Custom_Duty: 15%; Customs_HS_Code: 85332119; Distributor_name: DIGIKEY; Distributor_part_number: 541-0.0JCT-ND; Footprint Path: Y:\MIS_DATABASE\Library\ALTIUM_TOOL\PCB_FOOTPRINTS\Altium_Footprint_Lib.PcbLib; Height: 0.40MM; Library Path: Y:\MIS_DATABASE\Library\ALTIUM_TOOL\SCHEMATICS_PARTS\MS_DISCRETE_Library.schlib; Mfr_name: VISHAY; Mfr_part_number: CRCW04020000Z0ED; Mistral Part No: 110010080019-R; Package: 0402; Part_type: RESISTORS\FIXED; Project: PB_BUGBASE; RoHS: RoHS; SIGNAL_MODEL: RESISTOR_RES0402_0-5_0E_0E; Temperature: -55°C+155°C; Tolerance: NA; Voltage: NA; Wattage: 1/16W; Weight: 0.65mg; Datasheet: Y:\MIS_DATABASE\DATASHEETS\RESISTORS\CRCW0603.PDF
R634 = RESISTOR: RES 2.2K 1/20W 5% 0201; Chkd/date: MANIRAJA/310821; Crtd /date: ALVY/310821; Custom_Duty: 15%; Customs_HS_Code: 85332119; Distributor_name: DIGIKEY; Distributor_part_number: P123277CT-ND; Footprint Path: Y:\MIS_DATABASE\Library\ALTIUM_TOOL\PCB_FOOTPRINTS\Altium_Footprint_Lib.PcbLib; Height: 0.26MM; Library Path: Y:\MIS_DATABASE\Library\ALTIUM_TOOL\SCHEMATICS_PARTS\MS_DISCRETE_Library.schlib; Mfr_name: PANASONIC-ECG; Mfr_part_number: ERJ-1GNJ222C; Mistral Part No: 110009030427-R; Package: 0201; Part_type: RESISTORS\FIXED; Project: TI_AM335x SK_BRD; RoHS: RoHS; Temperature: -55°C+125°C; Tolerance: 5%; Voltage: NA; Wattage: 1/20W; Weight: 0.15mg; Datasheet: Y:\MIS_DATABASE\DATASHEETS\RESISTORS\PAN-ERJSER_NOV17.PDF
R635 R637 R638 R640 R642 R643 R645 R649 R650 = RESISTOR: RES 2.49K 1/16W 1% 0402; Assembly_Instruction: DNI; Chkd/date: VASANTHA/270516; Crtd /date: VASANTHA/270516; Custom_Duty: 15%; Customs_HS_Code: 85332119; Distributor_name: DIGIKEY; Distributor_part_number: 311-2.49KLRCT-ND; Footprint Path: Y:\MIS_DATABASE\Library\ALTIUM_TOOL\PCB_FOOTPRINTS\Altium_Footprint_Lib.PcbLib; Height: 0.40MM; Library Path: Y:\MIS_DATABASE\Library\ALTIUM_TOOL\SCHEMATICS_PARTS\MS_DISCRETE_Library.schlib; Mfr_name: YAGEO AMERICA; Mfr_part_number: RC0402FR-072K49L; Mistral Part No: 110016050020-R; Package: 0402; Part_type: RESISTORS\FIXED; Project: TMDXCSKCC; RoHS: RoHS; Temperature: -55°C+155°C; Tolerance: 1%; Voltage: NA; Wattage: 1/16W; Weight: 0.65mg; Datasheet: Y:\MIS_DATABASE\DATASHEETS\RESISTORS\RCXXXXL-SER_MAR18.PDF
R636 R653 = RESISTOR: RES 11K 1/16W 1% 0402; Chkd/date: VASANTHA/251115; Crtd /date: VASANTHA/251115; Custom_Duty: 15%; Customs_HS_Code: 85332119; Distributor_name: DIGIKEY; Distributor_part_number: 311-11.0KLRCT-ND; Footprint Path: Y:\MIS_DATABASE\Library\ALTIUM_TOOL\PCB_FOOTPRINTS\Altium_Footprint_Lib.PcbLib; Height: 0.40MM; Library Path: Y:\MIS_DATABASE\Library\ALTIUM_TOOL\SCHEMATICS_PARTS\MS_DISCRETE_Library.schlib; Mfr_name: YAGEO AMERICA; Mfr_part_number: RC0402FR-0711KL; Mistral Part No: 110015110012-R; Package: 0402; Part_type: RESISTORS\FIXED; Project: TI_VLAN_SWITCH; RoHS: RoHS; Temperature: -55°C+155°C; Tolerance: 1%; Voltage: NA; Wattage: 1/16W; Weight: 0.65mg; Datasheet: Y:\MIS_DATABASE\DATASHEETS\RESISTORS\RCXXXXL-SER_MAR18.PDF
R639 = RESISTOR: RES 0E 1/10W 5% 0603; Chkd/date: MANIRAJA/051217; Crtd /date: BAVISH/180211; Custom_Duty: 15%; Customs_HS_Code: 85332119; Distributor_name: DIGIKEY; Distributor_part_number: 311-0.0GRCT-ND; Footprint Path: Y:\MIS_DATABASE\Library\ALTIUM_TOOL\PCB_FOOTPRINTS\Altium_Footprint_Lib.PcbLib; Height: 0.55MM; Library Path: Y:\MIS_DATABASE\Library\ALTIUM_TOOL\SCHEMATICS_PARTS\MS_DISCRETE_Library.schlib; Mfr_name: YAGEO AMERICA; Mfr_part_number: RC0603JR-070RL; Mistral Part No: 110011020013-R; Package: 0603; Part_type: RESISTORS\FIXED; Project: KENNEL; RoHS: RoHS; Temperature: -55°C+155°C; Tolerance: 5%; Voltage: NA; Wattage: 1/10W; Weight: 2mg; Datasheet: Y:\MIS_DATABASE\DATASHEETS\RESISTORS\RCXXXXL-SER_MAR18.PDF
R644 R646 = RESISTOR: RES 0E 1/16W JUMPER 0402; Chkd/date: VASANTHA/201216; Crtd /date: MUDDU/190810; Custom_Duty: 15%; Customs_HS_Code: 85332119; Distributor_name: DIGIKEY; Distributor_part_number: 541-0.0JCT-ND; Footprint Path: Y:\MIS_DATABASE\Library\ALTIUM_TOOL\PCB_FOOTPRINTS\Altium_Footprint_Lib.PcbLib; Height: 0.40MM; Library Path: Y:\MIS_DATABASE\Library\ALTIUM_TOOL\SCHEMATICS_PARTS\MS_DISCRETE_Library.schlib; Mfr_name: VISHAY; Mfr_part_number: CRCW04020000Z0ED; Mistral Part No: 110010080019-R; Package: 0402; Part_type: RESISTORS\FIXED; Project: PB_BUGBASE; RoHS: RoHS; Temperature: -55°C+155°C; Tolerance: NA; Voltage: NA; Wattage: 1/16W; Weight: 0.65mg; Datasheet: Y:\MIS_DATABASE\DATASHEETS\RESISTORS\CRCW0603.PDF
R647 R655 R656 = RESISTOR: RES 220E 1/10W 5% 0402; Chkd/date: VASANTHA/291216; Crtd /date: GEETHA/260406; Custom_Duty: 15%; Customs_HS_Code: 85332119; Distributor_name: DIGIKEY; Distributor_part_number: P220JCT-ND; Footprint Path: Y:\MIS_DATABASE\Library\ALTIUM_TOOL\PCB_FOOTPRINTS\Altium_Footprint_Lib.PcbLib; Height: 0.40MM; Library Path: Y:\MIS_DATABASE\Library\ALTIUM_TOOL\SCHEMATICS_PARTS\MS_DISCRETE_Library.schlib; Mfr_name: PANASONIC-ECG; Mfr_part_number: ERJ-2GEJ221X; Mistral Part No: 110009030506-R; Package: 0402; Part_type: RESISTORS\FIXED; Project: RED EYE; RoHS: RoHS; Temperature: -55°C+155°C; Tolerance: 5%; Voltage: NA; Wattage: 1/10W; Weight: 0.8mg; Datasheet: Y:\MIS_DATABASE\DATASHEETS\RESISTORS\PAN-ERJSER_NOV17.PDF
R149 R648 R657 R658 R661 = RESISTOR: RES 10K 1/20W 5% 0201; Chkd/date: MANIRAJA/050517; Crtd /date: MANIRAJA/050517; Custom_Duty: 15%; Customs_HS_Code: 85332119; Distributor_name: DIGIKEY; Distributor_part_number: 311-10KNCT-ND; Footprint Path: Y:\MIS_DATABASE\Library\ALTIUM_TOOL\PCB_FOOTPRINTS\Altium_Footprint_Lib.PcbLib; Height: 0.26MM; Library Path: Y:\MIS_DATABASE\Library\ALTIUM_TOOL\SCHEMATICS_PARTS\MS_DISCRETE_Library.schlib; Mfr_name: YAGEO AMERICA; Mfr_part_number: RC0201JR-0710KL; Mistral Part No: 110010070051-R; Package: 0201; Part_type: RESISTORS\FIXED; Project: GOLDEN-I LITE; RoHS: RoHS; Temperature: -55°C+125°C; Tolerance: 5%; Voltage: NA; Wattage: 1/20W; Weight: 0.17mg; Datasheet: Y:\MIS_DATABASE\DATASHEETS\RESISTORS\RCXXXXL-SER_MAR18.PDF
R652 R659 = RESISTOR: RES 10K 1/20W 5% 0201; Assembly_Instruction: DNI; Chkd/date: MANIRAJA/050517; Crtd /date: MANIRAJA/050517; Custom_Duty: 15%; Customs_HS_Code: 85332119; Distributor_name: DIGIKEY; Distributor_part_number: 311-10KNCT-ND; Footprint Path: Y:\MIS_DATABASE\Library\ALTIUM_TOOL\PCB_FOOTPRINTS\Altium_Footprint_Lib.PcbLib; Height: 0.26MM; Library Path: Y:\MIS_DATABASE\Library\ALTIUM_TOOL\SCHEMATICS_PARTS\MS_DISCRETE_Library.schlib; Mfr_name: YAGEO AMERICA; Mfr_part_number: RC0201JR-0710KL; Mistral Part No: 110010070051-R; Package: 0201; Part_type: RESISTORS\FIXED; Project: GOLDEN-I LITE; RoHS: RoHS; Temperature: -55°C+125°C; Tolerance: 5%; Voltage: NA; Wattage: 1/20W; Weight: 0.17mg; Datasheet: Y:\MIS_DATABASE\DATASHEETS\RESISTORS\RCXXXXL-SER_MAR18.PDF
R654 = RESISTOR: RES 5.76K 1/10W 1% 0402; Assembly_Instruction: DNI; Chkd/date: MAZHAR/150709; Crtd /date: USMAN/220808; Custom_Duty: 15%; Customs_HS_Code: 85332119; Distributor_name: DIGIKEY; Distributor_part_number: P5.76KLCT-ND; Footprint Path: Y:\MIS_DATABASE\Library\ALTIUM_TOOL\PCB_FOOTPRINTS\Altium_Footprint_Lib.PcbLib; Height: 0.40MM; Library Path: Y:\MIS_DATABASE\Library\ALTIUM_TOOL\SCHEMATICS_PARTS\MS_DISCRETE_Library.schlib; Mfr_name: PANASONIC-ECG; Mfr_part_number: ERJ-2RKF5761X; Mistral Part No: 110009030945-R; Package: 0402; Part_type: RESISTORS\FIXED; Project: CPB; RoHS: RoHS; Temperature: -55°C+155°C; Tolerance: 1%; Voltage: NA; Wattage: 1/10W; Weight: 0.8mg; Datasheet: Y:\MIS_DATABASE\DATASHEETS\RESISTORS\PAN-ERJSER_NOV17.PDF
R660 = RESISTOR: RES 0E 1/20W 5% 0201; Assembly_Instruction: DNI; Chkd/date: NAVEED/301214; Crtd /date: MUDDU/120710; Custom_Duty: 15%; Customs_HS_Code: 85332119; Distributor_name: DIGIKEY; Distributor_part_number: 311-0.0NCT-ND; Footprint Path: Y:\MIS_DATABASE\Library\ALTIUM_TOOL\PCB_FOOTPRINTS\Altium_Footprint_Lib.PcbLib; Height: 0.26MM; Library Path: Y:\MIS_DATABASE\Library\ALTIUM_TOOL\SCHEMATICS_PARTS\MS_DISCRETE_Library.schlib; Mfr_name: YAGEO AMERICA; Mfr_part_number: RC0201JR-070RL; Mistral Part No: 110010070067-R; Package: 0201; Part_type: RESISTORS\FIXED; Project: PB_BUGBASE; RoHS: RoHS; Temperature: -55°C+125°C; Tolerance: 5%; Voltage: NA; Wattage: 1/20W; Weight: 0.17mg; Datasheet: Y:\MIS_DATABASE\DATASHEETS\RESISTORS\RCXXXXL-SER_MAR18.PDF
TP125-TP127 = TESTPOINT: TESTPOINT CIR 20 SMD; Chkd/date: SHREESHAIL/171006; Crtd /date: MAZHAR/171006; Custom_Duty: NA; Customs_HS_Code: NA; Distributor_name: NA; Distributor_part_number: NA; Footprint Path: Y:\MIS_DATABASE\Library\ALTIUM_TOOL\PCB_FOOTPRINTS\Altium_Footprint_Lib.PcbLib; Height: NA; Library Path: Y:\MIS_DATABASE\Library\ALTIUM_TOOL\SCHEMATICS_PARTS\MS_DISCRETE_Library.schlib; MECHANICAL 3D STEP FILE: NA; Manufacturer: LOCAL; Mfr_name: LOCAL; Mistral Part No: NA; Package: SMD; Project: BT MODULE_CSRBC04; RoHS: NA; Temperature: NA; Tolerance: NA; Voltage: NA; Wattage: NA; Weight: NA; Datasheet: NA
U127 = DP83867IRRGZ_VQFN48: IC HIGH IMMUNITY 10/100/1000 Mb/s ETHERNET PHY LAYER TRANSCEIVER VQFN48; Chkd/date: MANIRAJA/110817; Crtd /date: MANIRAJA/110817; Custom_Duty: 15%; Customs_HS_Code: 85423100; Distributor_name: DIGIKEY; Distributor_part_number: DP83867IRRGZT-ND; Height: 1.00MM; Mfr_name: TEXAS INSTRUMENTS; Mistral Part No: 143017080002-R; Package: VQFN48; Part_type: ICS\TELECOM\TRANSCEIVER; Project: TI_SVB_CONTROLLER CARD; RoHS: RoHS; Temperature: -40°C+85°C; Tolerance: NA; Voltage: NA; Wattage: NA; Weight: NA; Datasheet: Y:\MIS_DATABASE\DATASHEETS\ICS\DIGITAL\BUSTRANSCEIVER\DP83867I.PDF
U128 = SN74LVC1G11DCKR_SC70-6: IC SINGLE 3-INPUT POSITIVE-AND GATE SON6; Chkd/date: MANIRAJA/270121; Crtd /date: ALVY/270121; Custom_Duty: 15%; Customs_HS_Code: 85423100; Distributor_name: DIGIKEY; Distributor_part_number: 296-30120-1-ND; Footprint Path: Y:\MIS_DATABASE\Library\ALTIUM_TOOL\PCB_FOOTPRINTS\Altium_Footprint_Lib.PcbLib; Height: 0.60MM; Library Path: Y:\MIS_DATABASE\Library\ALTIUM_TOOL\SCHEMATICS_PARTS\MS_GATE_Library.schlib; Mfr_name: TEXAS INSTRUMENTS; Mistral Part No: 141021010013-R; Package: SON6; Part_type: ICS\DIGITAL\GATES; Project: AM64X_SKEVM; RoHS: RoHS; Temperature: -40°C+125°C; Tolerance: NA; Voltage: NA; Wattage: NA; Weight: 33mg; Datasheet: Y:\MIS_DATABASE\DATASHEETS\ICS\DIGITAL\GATES\SN74LVC1G_NOV16.PDF
D4 = DIODE_SOD323: DIODE 1CH ESD PROTECTION X1SON2; Chkd/date: MANIRAJA/040420; Crtd /date: VASANTHA/181114; Custom_Duty: 15%; Customs_HS_Code: 85423100; Distributor_name: DIGIKEY; Distributor_part_number: 296-30406-1-ND; Footprint Path: Y:\MIS_DATABASE\Library\ALTIUM_TOOL\PCB_FOOTPRINTS\Altium_Footprint_Lib.PcbLib; Height: 0.45MM; Library Path: Y:\MIS_DATABASE\Library\ALTIUM_TOOL\SCHEMATICS_PARTS\MS_DISCRETE_Library.schlib; Mfr_name: TEXAS INSTRUMENTS; Mistral Part No: 130014110022-R; Package: X1SON2; Part_type: DIODE; Project: GALILEO_EVM; RoHS: RoHS; Temperature: -40°C+125°C; Tolerance: NA; Voltage: NA; Wattage: NA; Weight: 1mg; Datasheet: Y:\MIS_DATABASE\DATASHEETS\ICS\INTERFACE\TPD1E10B06-SER.PDF
SW2 = 7914G-1-000E__7914G: SWITCH SPST-NO 4MM SQ SMD 7914G; Chkd/date: VASANTHA/271216; Crtd /date: BAVISH/051010; Custom_Duty: 24%; Customs_HS_Code: 85369090; Distributor_name: DIGIKEY; Distributor_part_number: 7914G-000ECT-ND; Height: 4.19MM; Library Ref: 7914G-1-000E _7914G; Mfr_name: BOURNS; Mistral Part No: 130015110004-R; Package: 7914G; Part_type: ELECTRO-MECHANICAL\SWITCH; Project: AAAUC; RoHS: RoHS; Temperature: -55°C+125°C; Tolerance: NA; Voltage: NA; Wattage: NA; Weight: NA; Datasheet: Y:\MIS_DATABASE\DATASHEETS\ICS\DIGITAL\COMBINATIONAL\7914G-1-000E.PDF
U27 = SN74LVC3G17DCUR_VSSOP8: IC TRIPLE SCHMITT-TRIGGER BUFFER VSSOP8; Chkd/date: MANIRAJA/280917; Crtd /date: MANIRAJA/280917; Custom_Duty: 15%; Customs_HS_Code: 85423100; Distributor_name: DIGIKEY; Distributor_part_number: 296-18818-1-ND; Height: 0.90MM; Mfr_name: TEXAS INSTRUMENTS; Mistral Part No: 141017090019-R; Package: VSSOP8; Part_type: ICS\DIGITAL\COMBINATIONAL; Project: TI_MAXIE_CPB; RoHS: RoHS; Temperature: -40°C+125°C; Tolerance: NA; Voltage: NA; Wattage: NA; Weight: 9.6mg; Datasheet: Y:\MIS_DATABASE\DATASHEETS\ICS\DIGITAL\COMBINATIONAL\SN74LVC3G17.PDF

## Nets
DGND: C72.1 C74.2 C78.2 C80.1 C83.1 C88.2 C90.1 C91.1 C92.1 C93.1 C94.1 C95.1 C97.1 C98.2 C99.1 C104.1 C105.1 C106.2 C114.1 C115.2 C330.1 C331.1 C332.1 C336.1 C337.1 C339.1 C346.1 C347.1 C353.1 C355.1 C356.1 C357.1 C360.2 C366.2 C367.1 C562.1 C563.2 C564.2 C565.2 C566.2 C567.2 C568.2 C569.2 C570.2 C571.2 C572.2 C573.2 C574.2 C575.2 C576.2 C577.2 C578.2 C579.2 C580.2 C581.2 C582.2 C583.2 C584.2 C585.2 C586.2 C587.2 C588.2 D4.1 J27.1(CH-GND) Q19.4(S1) Q19.7(S2) Q20.4(S1) Q20.7(S2) Q21.4(S1) Q21.7(S2) R94.1 R375.2 R631.1 R633.1 R635.1 R636.2 R637.1 R638.1 R639.2 R643.1 R649.1 R659.2 R661.2 SW2.1 SW2.4 U20.A3(VSS) U20.A10(VSS) U20.AB3(VSS) U20.AB5(VSS) U20.AB8(VSS) U20.AB10(VSS) U20.C1(VSS) U20.C5(VSS) U20.C8(VSS) U20.C12(VSS) U20.D2(VSS) U20.D4(VSS) U20.D9(VSS) U20.D11(VSS) U20.E1(VSS) U20.E5(VSS) U20.E8(VSS) U20.E12(VSS) U20.G1(VSS) U20.G3(VSS) U20.G5(VSS) U20.G8(VSS) U20.G10(VSS) U20.G12(VSS) U20.J1(VSS) U20.J3(VSS) U20.J10(VSS) U20.J12(VSS) U20.K2(VSS) U20.K4(VSS) U20.K9(VSS) U20.K11(VSS) U20.N2(VSS) U20.N4(VSS) U20.N9(VSS) U20.N11(VSS) U20.P1(VSS) U20.P3(VSS) U20.P10(VSS) U20.P12(VSS) U20.T1(VSS) U20.T3(VSS) U20.T5(VSS) U20.T8(VSS) U20.T10(VSS) U20.T12(VSS) U20.V1(VSS) U20.V5(VSS) U20.V8(VSS) U20.V12(VSS) U20.W2(VSS) U20.W4(VSS) U20.W9(VSS) U20.W11(VSS) U20.Y1(VSS) U20.Y5(VSS) U20.Y8(VSS) U20.Y12(VSS) U27.4(GND) U127.49(GND) U128.2(GND) ; also on sheet 4 13 14 15 16 17 18 19 20 21 22 23 24 25 26 27 28 29 30 31 32 33 34 35 36 37 38 39 40 41 42 43
VCC_3V3_SYS: C563.1 C567.1 C570.1 C577.1 C579.1 C581.1 C583.1 C585.1 C588.1 FL22.1 R630.1 R634.2 R640.2 R642.2 R645.2 R647.1 R648.2 R650.2 R652.2 R653.2 R654.1 R655.2 R656.2 R657.2 R658.2 U127.19(VDDIO) U127.30(VDDIO) U127.41(VDDIO) U128.5(VCC) ; also on sheet 4 15 16 19 20 21 23 24 26 27 29 30 31 32 33 34 36 37 38 39 40 41 42 43
VDD1_LPDDR4_1V8: C78.1 C80.2 C88.1 C90.2 C91.2 C94.2 C95.2 C332.2 C337.2 C353.2 C355.2 FL10.2 U20.F1(VDD1) U20.F12(VDD1) U20.G4(VDD1) U20.G9(VDD1) U20.T4(VDD1) U20.T9(VDD1) U20.U1(VDD1) U20.U12(VDD1)
VDD_1V0: C564.1 C565.1 C568.1 C569.1 C572.1 C574.1 C576.1 C578.1 C580.1 C586.1 U127.6(VDD1P0) U127.24(VDD1P0) U127.31(VDD1P0) U127.42(VDD1P0) ; also on sheet 15 24
VDD_2V5: C566.1 C573.1 C575.1 C582.1 C584.1 C587.1 U127.3(VDDA2P5) U127.9(VDDA2P5) ; also on sheet 15 24
VDD_LPDDR4: C72.2 C74.1 C83.2 C92.2 C93.2 C97.2 C98.1 C99.2 C104.2 C105.2 C106.1 C330.2 C331.2 C336.2 C339.2 C346.2 C347.2 C356.2 C357.2 C360.1 C366.1 C367.2 R93.2 R100.1 R384.2 U20.A4(VDD2) U20.A9(VDD2) U20.AA3(VDDQ) U20.AA5(VDDQ) U20.AA8(VDDQ) U20.AA10(VDDQ) U20.AB4(VDD2) U20.AB9(VDD2) U20.B3(VDDQ) U20.B5(VDDQ) U20.B8(VDDQ) U20.B10(VDDQ) U20.D1(VDDQ) U20.D5(VDDQ) U20.D8(VDDQ) U20.D12(VDDQ) U20.F3(VDDQ) U20.F5(VDD2) U20.F8(VDD2) U20.F10(VDDQ) U20.H1(VDD2) U20.H5(VDD2) U20.H8(VDD2) U20.H12(VDD2) U20.K1(VDD2) U20.K3(VDD2) U20.K10(VDD2) U20.K12(VDD2) U20.N1(VDD2) U20.N3(VDD2) U20.N10(VDD2) U20.N12(VDD2) U20.R1(VDD2) U20.R5(VDD2) U20.R8(VDD2) U20.R12(VDD2) U20.U3(VDDQ) U20.U5(VDD2) U20.U8(VDD2) U20.U10(VDDQ) U20.W1(VDDQ) U20.W5(VDDQ) U20.W8(VDDQ) U20.W12(VDDQ) ; also on sheet 16 17 18
VDDSHV_CANUART: C115.1 R149.1 U27.8(VCC) ; also on sheet 4 17 31 32
CAN_FD_WKUP_SW_INH: U27.7(1Y) ; also on sheet 32
CPSW2_GPIO_0: J27.14 Q20.1(D1) Q20.2(D2) Q20.5(D3) Q20.6(D4) Q20.8(D5) R656.1
CPSW2_LED_1000: J27.12 Q19.1(D1) Q19.2(D2) Q19.5(D3) Q19.6(D4) Q19.8(D5)
CPSW2_LED_ACT: J27.13 Q21.1(D1) Q21.2(D2) Q21.5(D3) Q21.6(D4) Q21.8(D5) R655.1
CPSW_ETH2_D0N: J27.10(MX0-) U127.2(TD_M_A)
CPSW_ETH2_D0P: J27.9(MX0+) U127.1(TD_P_A)
CPSW_ETH2_D1M: J27.8(MX1-) U127.5(TD_M_B)
CPSW_ETH2_D1P: J27.7(MX1+) U127.4(TD_P_B)
CPSW_ETH2_D2M: J27.6(MX2-) U127.8(TD_M_C)
CPSW_ETH2_D2P: J27.5(MX2+) U127.7(TD_P_C)
CPSW_ETH2_D3M: J27.4(MX3-) U127.11(TD_M_D)
CPSW_ETH2_D3P: J27.3(MX3+) U127.10(TD_P_D)
CPSW_ETH2_GPIO_0: R627.1 R641.1 R643.2 R645.1 TP121.1(TP)
CPSW_ETH2_GPIO_1: R628.1 R642.1 R649.2 TP122.1(TP)
CPSW_ETH2_LED0: TP123.1(TP) U127.47(LED_0)
CPSW_ETH2_LED_1000: R629.1 R633.2 R648.1 TP119.1(TP) U127.46(LED_1)
CPSW_ETH2_LED_ACT: R638.2 R650.1 R651.1 TP120.1(TP) U127.45(LED_2)
CPSW_RGMII1_ETH2_RBIAS: C562.2 R636.1 U127.12(RBIAS)
CPSW_RGMII2_ETH2_CLK: U127.15(XI) ; also on sheet 25
CPSW_RGMII2_ETH2_CLK_OUT: TP124.1(TP) U127.18(CLK_OUT)
CPSW_RGMII2_MDC: R644.2 R652.1 U127.16(MDC)
CPSW_RGMII2_MDIO: R630.2 R646.2 U127.17(MDIO)
CPSW_RGMII2_RD0: R631.2 R653.1 U127.33(RX_D0) ; also on sheet 25
CPSW_RGMII2_RD1: U127.34(RX_D1) ; also on sheet 25
CPSW_RGMII2_RD2: R637.2 R640.1 U127.35(RX_D2) ; also on sheet 25
CPSW_RGMII2_RD3: U127.36(RX_D3) ; also on sheet 25
CPSW_RGMII2_RESETn: R661.1 U127.43(RESET_N) U128.4(Y)
CPSW_RGMII2_RX_CTL: R635.2 R654.2 U127.38(RX_DV/RX_CTRL) ; also on sheet 25
CPSW_RGMII2_RXC: R632.1 ; also on sheet 25
CPSW_RGMII2_TD0: U127.28(TX_D0) ; also on sheet 25
CPSW_RGMII2_TD1: U127.27(TX_D1) ; also on sheet 25
CPSW_RGMII2_TD2: U127.26(TX_D2) ; also on sheet 25
CPSW_RGMII2_TD3: U127.25(TX_D3) ; also on sheet 25
CPSW_RGMII2_TX_CTL: U127.37(TX_EN/TX_CTRL) ; also on sheet 25
CPSW_RGMII2_TXC: U127.29(GTX_CLK) ; also on sheet 25
CPSW_RGMII_INTn: R634.1 U127.44(INT/PWDN) ; also on sheet 24
DEBOUNCE_CAN_FD_WKUP: C114.2 D4.2 R149.2 SW2.2 SW2.3 U27.1(1A)
ETH2_EARTH: C571.1 J27.15(SH1) J27.16(SH2) R639.1
GPIO_CPSW2_RST: R658.1 R659.1 U128.1(A) ; also on sheet 39
LPDDR4_CA0: U12.F5(DDR0_A0) U20.H2(CA0)
LPDDR4_CA1: U12.G5(DDR0_A1) U20.J2(CA1)
LPDDR4_CA2: U12.G4(DDR0_A2) U20.H9(CA2)
LPDDR4_CA3: U12.H4(DDR0_A3) U20.H10(CA3)
LPDDR4_CA4: U12.J5(DDR0_A4) U20.H11(CA4)
LPDDR4_CA5: U12.H5(DDR0_A5) U20.J11(CA5)
LPDDR4_CAL0: R375.1 U12.K4(DDR0_CAL0)
LPDDR4_CK_N: U12.K1(DDR0_CK0_N) U20.J9(CK_C)
LPDDR4_CK_P: U12.J1(DDR0_CK0) U20.J8(CK_T)
LPDDR4_CKE: U12.G3(DDR0_CKE0) U20.J4(CKE)
LPDDR4_CS: U12.H3(DDR0_CS0_N) U20.H4(CS)
LPDDR4_CS1_N: TP30.1(TP) U12.G1(DDR0_CS1_N)
LPDDR4_DMI0: U12.E3(DDR0_DM0) U20.C3(DMI0)
LPDDR4_DMI1: U12.R4(DDR0_DM1) U20.C10(DMI1)
LPDDR4_DQ0: U12.C2(DDR0_DQ0) U20.B2(DQ0)
LPDDR4_DQ1: U12.E4(DDR0_DQ1) U20.C2(DQ1)
LPDDR4_DQ2: U12.D3(DDR0_DQ2) U20.E2(DQ2)
LPDDR4_DQ3: U12.E5(DDR0_DQ3) U20.F2(DQ3)
LPDDR4_DQ4: U12.D2(DDR0_DQ4) U20.F4(DQ4)
LPDDR4_DQ5: U12.F3(DDR0_DQ5) U20.E4(DQ5)
LPDDR4_DQ6: U12.F1(DDR0_DQ6) U20.C4(DQ6)
LPDDR4_DQ7: U12.F2(DDR0_DQ7) U20.B4(DQ7)
LPDDR4_DQ8: U12.R3(DDR0_DQ8) U20.B11(DQ8)
LPDDR4_DQ9: U12.R2(DDR0_DQ9) U20.C11(DQ9)
LPDDR4_DQ10: U12.T2(DDR0_DQ10) U20.E11(DQ10)
LPDDR4_DQ11: U12.U2(DDR0_DQ11) U20.F11(DQ11)
LPDDR4_DQ12: U12.U3(DDR0_DQ12) U20.F9(DQ12)
LPDDR4_DQ13: U12.U4(DDR0_DQ13) U20.E9(DQ13)
LPDDR4_DQ14: U12.T4(DDR0_DQ14) U20.C9(DQ14)
LPDDR4_DQ15: U12.T5(DDR0_DQ15) U20.B9(DQ15)
LPDDR4_DQS0_N: U12.E1(DDR0_DQS0_N) U20.E3(DQS0_C)
LPDDR4_DQS0_P: U12.D1(DDR0_DQS0) U20.D3(DQS0_T)
LPDDR4_DQS1_N: U12.R1(DDR0_DQS1_N) U20.E10(DQS1_C)
LPDDR4_DQS1_P: U12.T1(DDR0_DQS1) U20.D10(DQS1_T)
LPDDR4_ODT_CA: R384.1 U20.G2(ODT_CA)
LPDDR4_RESET_N: R93.1 R94.2 U12.G2(DDR0_RESET0_N) U20.T11(RESET_n)
LPDDR4_ZQ: R100.2 U20.A5(ZQ)
PORz_OUT: U128.3(B) ; also on sheet 21 24 27 42
RESETSTATz: R660.1 ; also on sheet 4 20 21 22 24 27 32 37 38 39 40 41 42
SOC_DVDD1V8: FL10.1 ; also on sheet 16 17 18
SoC_RGMII_MDC: R644.1 ; also on sheet 24 32
SoC_RGMII_MDIO: R646.1 ; also on sheet 24 32
N22622854: FL22.2 J27.2(VCC)
N22622886: R628.2 U127.40(GPIO_1)
N22622904: R627.2 U127.39(GPIO_0)
N22623025: R632.2 U127.32(RX_CLK)
N22623655: TP125.1(TP) U127.48(VDDA1P8)
N22623691: TP126.1(TP) U127.14(XO)
N22623898: TP127.1(TP) U127.13(VDDA1P8)
N22624142: Q19.3(G) R629.2
N22624353: Q20.3(G) R641.2
N22624355: Q21.3(G) R651.2
N22624429: J27.11 R647.2
N22624465: R657.1 R660.2 U128.6(C)

Not connected (* = marked no-connect by the designer): U12 H2(DDR0_CKE1) J2(DDR0_WE_N) J3(DDR0_CAS_N) J4(DDR0_ODT0) K2(DDR0_ODT1) K5(DDR0_RAS_N) L2(DDR0_BG1) L3(DDR0_BA1) L4(DDR0_BG0) L5(DDR0_BA0) M1(DDR0_ACT_N) M2(DDR0_PAR) M3(DDR0_A11) M4(RSVD7) M5(RSVD8) N1(DDR0_ALERT_N) N2(DDR0_A7) N3(DDR0_A10) N4(DDR0_A9) N5(DDR0_A13) P2(DDR0_A8) P4(DDR0_A6) P5(DDR0_A12); U20 A1(DNU1) A2(DNU2) A8(NC1)* A11(DNU3) A12(DNU4) AA1(DNU7) AA2(NC40) AA4(NC41) AA9(NC42) AA11(NC43) AA12(DNU8) AB1(DNU9)* AB2(DNU10)* AB11(DNU11)* AB12(DNU12)* B1(DNU5) B12(DNU6) G11(NC2)* H3(NC3)* J5(NC4)* K5(NC5)* K8(NC6)* N5(NC7) N8(NC8) P2(NC10) P4(NC11) P5(NC12) P8(NC13) P9(NC14) P11(NC9) R2(NC17) R3(NC18) R4(NC19) R9(NC20) R10(NC15) R11(NC16) T2(NC21) U2(NC23) U4(NC24) U9(NC25) U11(NC22) V2(NC28) V3(NC29) V4(NC30) V9(NC31) V10(NC26) V11(NC27) W3(NC33) W10(NC32) Y2(NC36) Y3(NC37) Y4(NC38) Y9(NC39) Y10(NC34) Y11(NC35); U27 2(3Y)* 3(2A)* 5(2Y)* 6(3A)*; U127 20(JTAG_CLK)* 21(JTAG_TDO)* 22(JTAG_TMS)* 23(JTAG_TDI)*

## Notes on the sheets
sheet 1
- CPSW3G RGMII 2 - ETHERNET PHY
- D-Note :-
  The caps and values used are  as per the EPHY
  data sheet recommendations
- D-Note :-
  Refer to DP83867ERGZ-R-EVM when
  using LAN Discrete Transformer
  Module and RJ45 connector
- R-Note :-
  Ferrite is DNI
- D-Note :-
  Verify the power sequence
  requirements for Two-Supply
  Configuration and Three-Supply
  Configuration
- RJ45 CONNECTOR WITH
  INTEGRATED MAGNETICS
- 100E
- 100E
- D-Note :-
  Provide provision for Series resistor based
  on EPHY for RX signals near to EPHY
- 100E
- 100E
- D-Note :-
  XI clock Input amplitude allowed is 1.8V
  irrespective of the IO supply
  Use a CAP DIVIDER  when the clock amplified
  is 3.3V
- D-Note :-
  Refer EPHY EVM for JTAG connections
- Note :-
  Add a isolation resistor to the GPIO input
  for isolation or testing
  Refer SK-AM62P-LP schematics
- Silk: RGMII-2
- D-Note
  Anding logic could be optimized to 2 input AND gate
  Use RESETSTATz (or PORz_OUT) and the SoC IO as inputs
- Note :-
  Pullup is enabled for GPIO input
  RESETSTATz series resistor is DNI
- D-Note :-
  ANDing logic additionally performs level translation
  Verify the Reset IO level compatibility before
  optimizing the reset ANDing logic.
  IO level mismatch could cause supply leakage and
  affect SOC operation
- PHY ADDRESS = 0001
- Auto-negotiation Disabled
- 10/100/1000 advertised, Auto-MDI-X
- Tx Clock Skew = 0ns
- Rx Clock Skew = 2ns
sheet 2
- CAN-FD FAST WAKE UP SW
- Silk: RST
- D-Note:-
  Terminate  unused IOs as per the device data
  sheet recommendations
sheet 3
- SOC LPDDR4 INTERFACE
- LPDDR4 POWER DECAPS
- VDDQ_LPDDR4_1V1
- VDD2_LPDDR4_1V1
- LPDDR4 DEVICE
- R-Note :-
  Pulldown is populated
- D-Note :-
  10 K pulldown is
  recommended
  Refer Processor
  specific DDR design
  guide
